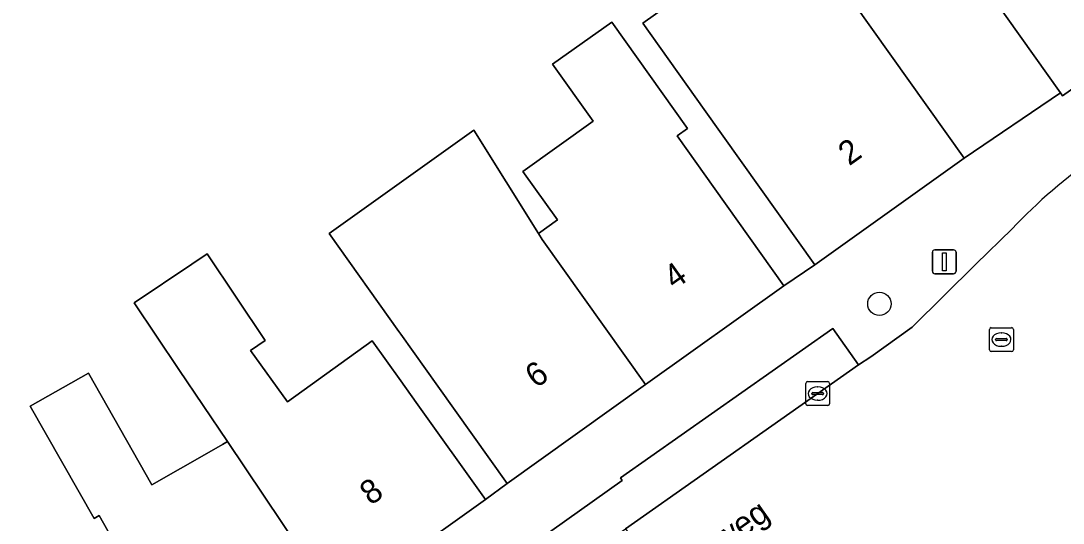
# Model space of a CAD drawing. Extents: x 161838 to 162344, y 381620 to 382160.
# Drawn here: x 161984.06 to 162027.79, y 381958.41 to 381979.46 of the extents above; entities that cross this region are included whole.
import ezdxf

# ---------------------------------------------------------------- set-up
doc = ezdxf.new("R2010")
doc.units = 0
for name, color, linetype in [('IMGEO_Boom', 7, 'Continuous'), ('IMGEO_Erf', 7, 'Continuous'), ('IMGEO_Kolk', 7, 'Continuous'), ('IMGEO_Lichtmast', 7, 'Continuous'), ('IMGEO_Openbare_ruimte_label', 7, 'Continuous'), ('IMGEO_Pand', 7, 'Continuous'), ('IMGEO_Pand_nummerreeks', 7, 'Continuous'), ('IMGEO_Parkeervlak_open', 7, 'Continuous'), ('IMGEO_Rijbaan_lokaal_open', 7, 'Continuous'), ('IMGEO_Rioolput', 7, 'Continuous'), ('IMGEO_Voetpad_open', 7, 'Continuous')]:
    doc.layers.add(name, color=color, linetype=linetype)

msp = doc.modelspace()

# ---------------------------------------------------------------- linework, layer by layer
at = {"layer": 'IMGEO_Boom'}
msp.add_circle((162020.08, 381967.6), 0.489, dxfattribs=at)
at = {"layer": 'IMGEO_Erf'}
msp.add_lwpolyline([(161988.92, 381955.966), (161987.349, 381958.724), (161987.136, 381958.603), (161984.457, 381963.308), (161986.895, 381964.696), (161989.559, 381960.019), (161991.967, 381961.39), (161992.526, 381961.708), (161992.731, 381961.825), (161990.696, 381964.855), (161988.821, 381967.646), (161991.235, 381969.267), (161991.877, 381969.698), (161994.317, 381966.065), (161993.698, 381965.649), (161995.244, 381963.494), (161998.796, 381966.044), (162000.007, 381964.371), (162000.65, 381963.47), (162003.552, 381959.398), (162004.459, 381960.074), (162001.557, 381964.146), (162000, 381966.33), (161999.916, 381966.448), (161996.996, 381970.544), (162003.07, 381974.874), (162005.776, 381970.545), (162006.579, 381971.117), (162005.126, 381973.155), (162008.07, 381975.253), (162006.368, 381977.641), (162008.849, 381979.41), (162012.028, 381974.95), (162011.593, 381974.64), (162013.172, 381972.425), (162016.075, 381968.353), (162017.37, 381969.238), (162012.728, 381975.752), (162010.152, 381979.367), (162013.737, 381981.922)], dxfattribs=at)
at = {"layer": 'IMGEO_Kolk'}
for p, q in [((162016.989, 381963.414), (162016.989, 381964.266)), ((162017.064, 381964.34), (162017.916, 381964.34)), ((162017.477, 381964.12), (162017.502, 381964.12)), ((162017.99, 381964.266), (162017.99, 381963.414)), ((162017.248, 381963.834), (162017.248, 381963.846)), ((162017.686, 381963.797), (162017.288, 381963.797)), ((162017.291, 381963.883), (162017.689, 381963.883)), ((162017.732, 381963.846), (162017.732, 381963.834)), ((162017.916, 381963.34), (162017.064, 381963.34)), ((162017.5, 381963.56), (162017.475, 381963.56))]:
    msp.add_line(p, q, dxfattribs=at)
for points in [[(162016.989, 381963.414), (162016.989, 381964.266)], [(162017.064, 381964.34), (162017.916, 381964.34)], [(162017.99, 381964.266), (162017.99, 381963.414)], [(162017.916, 381963.34), (162017.064, 381963.34)]]:
    msp.add_lwpolyline(points, dxfattribs=at)
for centre, radius, start, end in [((162017.066, 381964.264), 0.0765, 91.552, 178.448), ((162017.066, 381964.264), 0.0765, 91.552, 178.448), ((162017.914, 381964.264), 0.0765, 1.552, 88.448), ((162017.914, 381964.264), 0.0765, 1.552, 88.448), ((162017.288, 381963.843), 0.0403, 85.8775, 175.7526), ((162017.285, 381963.833), 0.0366, 178.938, 274.7102), ((162017.689, 381963.84), 0.043, 264.8664, 352.4533), ((162017.693, 381963.845), 0.0386, 1.7309, 96.639), ((162017.066, 381963.416), 0.0765, 181.552, 268.448), ((162017.066, 381963.416), 0.0765, 181.552, 268.448), ((162017.914, 381963.416), 0.0765, 271.552, 358.448), ((162017.914, 381963.416), 0.0765, 271.552, 358.448)]:
    msp.add_arc(centre, radius, start, end, dxfattribs=at)
for centre, major_axis, ratio, start_param, end_param in [((162017.476, 381963.84), (-0.387, 0.002), 0.722429, 4.712389, 7.853982), ((162017.501, 381963.84), (-0.39, 0.002), 0.717154, 1.570796, 4.712389)]:
    msp.add_ellipse(centre, major_axis=major_axis, ratio=ratio, start_param=start_param, end_param=end_param, dxfattribs=at)
at = {"layer": 'IMGEO_Lichtmast'}
for p, q in [((162022.305, 381968.964), (162022.305, 381969.764)), ((162022.305, 381969.764), (162022.305, 381968.964)), ((162022.405, 381969.864), (162023.195, 381969.864)), ((162023.195, 381969.864), (162022.405, 381969.864)), ((162023.295, 381969.764), (162023.295, 381968.964)), ((162023.295, 381968.964), (162023.295, 381969.764)), ((162023.195, 381968.864), (162022.405, 381968.864)), ((162022.405, 381968.864), (162023.195, 381968.864))]:
    msp.add_line(p, q, dxfattribs=at)
msp.add_lwpolyline([(162022.725, 381969.739), (162022.875, 381969.739), (162022.875, 381968.989), (162022.725, 381968.989), (162022.725, 381969.739)], dxfattribs=at)
for centre, start, end in [((162022.405, 381969.764), 90, 180), ((162022.405, 381969.764), 90, 180), ((162023.195, 381969.764), 0, 90), ((162023.195, 381969.764), 360, 90), ((162022.405, 381968.964), 180, 270), ((162022.405, 381968.964), 180, 270), ((162023.195, 381968.964), 270, 0), ((162023.195, 381968.964), 270, 0)]:
    msp.add_arc(centre, 0.1, start, end, dxfattribs=at)
at = {"layer": 'IMGEO_Pand'}
for points in [[(162040.582, 381994.632), (162028.222, 381985.965), (162028.031, 381986.231), (162023.191, 381982.763), (162027.675, 381976.439), (162027.763, 381976.315), (162044.198, 381987.972), (162044.947, 381988.503), (162043.64, 381990.335), (162043.453, 381990.598)], [(162023.633, 381973.703), (162018.99, 381980.218), (162017.025, 381982.975), (162014.347, 381981.067), (162013.737, 381981.922), (162010.152, 381979.367), (162012.728, 381975.752), (162017.37, 381969.238)], [(162011.593, 381974.64), (162012.028, 381974.95), (162008.849, 381979.41), (162006.368, 381977.641), (162008.07, 381975.253), (162005.126, 381973.155), (162006.579, 381971.117), (162005.776, 381970.545), (162005.93, 381970.299), (162010.268, 381964.214), (162016.075, 381968.353), (162013.172, 381972.425)], [(162005.776, 381970.545), (162003.07, 381974.874), (161996.996, 381970.544), (161999.916, 381966.448), (162000, 381966.33), (162001.557, 381964.146), (162004.459, 381960.074), (162010.268, 381964.214), (162005.93, 381970.299)], [(161992.731, 381961.825), (161997.314, 381955), (161997.98, 381955.381), (161999.988, 381956.857), (162003.552, 381959.398), (162000.65, 381963.47), (162000.007, 381964.371), (161998.796, 381966.044), (161995.244, 381963.494), (161993.698, 381965.649), (161994.317, 381966.065), (161991.877, 381969.698), (161991.235, 381969.267), (161988.821, 381967.646), (161990.696, 381964.855)], [(161992.731, 381961.825), (161992.526, 381961.708), (161991.967, 381961.39), (161989.559, 381960.019), (161986.895, 381964.696), (161984.457, 381963.308), (161987.136, 381958.603), (161987.349, 381958.724), (161988.92, 381955.966), (161991.394, 381951.62), (161997.314, 381955)]]:
    msp.add_lwpolyline(points, close=True, dxfattribs=at)
at = {"layer": 'IMGEO_Parkeervlak_open'}
msp.add_lwpolyline([(161972.482, 381935.56), (161972.584, 381935.619), (161974.917, 381936.979), (162000, 381951.624), (162005.452, 381955.402), (162009.423, 381958.174), (162019.209, 381965.048), (162018.131, 381966.571), (162009.22, 381960.309), (162009.295, 381960.196), (162002.756, 381955.558), (162000, 381953.557), (161999.035, 381952.878), (161982.723, 381943.483), (161973.533, 381938.154), (161972.911, 381937.782)], dxfattribs=at)
at = {"layer": 'IMGEO_Rijbaan_lokaal_open'}
msp.add_lwpolyline([(162019.699, 381987.686), (162016.287, 381992.222), (162016.072, 381992.055), (162011.974, 381997.652), (162008.706, 381995.389), (162008.587, 381995.307), (162010.905, 381991.921), (162011.519, 381991.023), (162017.025, 381982.975), (162018.99, 381980.218), (162023.633, 381973.703), (162027.675, 381976.439), (162023.191, 381982.763)], close=True, dxfattribs=at)
msp.add_lwpolyline([(162025.649, 381970.744), (162024.131, 381969.266), (162021.458, 381966.619), (162019.719, 381965.377), (162019.209, 381965.048), (162009.423, 381958.174), (162012.054, 381954.611), (162018.349, 381956.152), (162021.392, 381956.878)], dxfattribs=at)
msp.add_arc((162042.038, 381955.244), 22.558, 124.7269, 136.5982, dxfattribs=at)
at = {"layer": 'IMGEO_Rioolput'}
for p, q in [((162024.699, 381965.676), (162024.699, 381966.528)), ((162024.774, 381966.602), (162025.626, 381966.602)), ((162025.187, 381966.382), (162025.212, 381966.382)), ((162025.7, 381966.528), (162025.7, 381965.676)), ((162024.958, 381966.096), (162024.958, 381966.108)), ((162025.396, 381966.059), (162024.998, 381966.059)), ((162025.001, 381966.145), (162025.399, 381966.145)), ((162025.442, 381966.108), (162025.442, 381966.096)), ((162025.626, 381965.602), (162024.774, 381965.602)), ((162025.21, 381965.822), (162025.185, 381965.822))]:
    msp.add_line(p, q, dxfattribs=at)
for points in [[(162024.699, 381965.676), (162024.699, 381966.528)], [(162024.774, 381966.602), (162025.626, 381966.602)], [(162025.7, 381966.528), (162025.7, 381965.676)], [(162025.626, 381965.602), (162024.774, 381965.602)]]:
    msp.add_lwpolyline(points, dxfattribs=at)
for centre, radius, start, end in [((162024.776, 381966.526), 0.0765, 91.552, 178.448), ((162024.776, 381966.526), 0.0765, 91.552, 178.448), ((162025.624, 381966.526), 0.0765, 1.552, 88.448), ((162025.624, 381966.526), 0.0765, 1.552, 88.448), ((162024.998, 381966.105), 0.0403, 85.8775, 175.7526), ((162024.995, 381966.095), 0.0366, 178.938, 274.7102), ((162025.399, 381966.102), 0.043, 264.8664, 352.4533), ((162025.403, 381966.107), 0.0386, 1.7309, 96.639), ((162024.776, 381965.678), 0.0765, 181.552, 268.448), ((162024.776, 381965.678), 0.0765, 181.552, 268.448), ((162025.624, 381965.678), 0.0765, 271.552, 358.448), ((162025.624, 381965.678), 0.0765, 271.552, 358.448)]:
    msp.add_arc(centre, radius, start, end, dxfattribs=at)
for centre, major_axis, ratio, start_param, end_param in [((162025.186, 381966.102), (-0.387, 0.002), 0.722429, 4.712389, 7.853982), ((162025.211, 381966.102), (-0.39, 0.002), 0.717154, 1.570796, 4.712389)]:
    msp.add_ellipse(centre, major_axis=major_axis, ratio=ratio, start_param=start_param, end_param=end_param, dxfattribs=at)
at = {"layer": 'IMGEO_Voetpad_open'}
for points in [[(162044.198, 381987.972), (162027.763, 381976.315), (162027.675, 381976.439), (162023.633, 381973.703), (162017.37, 381969.238), (162016.075, 381968.353), (162010.268, 381964.214), (162004.459, 381960.074), (162003.552, 381959.398), (161999.988, 381956.857), (161997.98, 381955.381), (161997.314, 381955), (161991.394, 381951.62), (161990.45, 381950.969), (161985.242, 381948.014), (161980.473, 381945.309), (161975.721, 381942.613), (161974.954, 381942.172), (161969.673, 381939.049), (161967.538, 381937.787), (161959.912, 381939.177), (161958.703, 381939.397), (161937.628, 381943.237), (161912.446, 381947.826)], [(161972.911, 381937.782), (161973.533, 381938.154), (161982.723, 381943.483), (161999.035, 381952.878), (162000, 381953.557), (162002.756, 381955.558), (162009.295, 381960.196), (162009.22, 381960.309), (162018.131, 381966.571), (162019.209, 381965.048), (162019.719, 381965.377), (162021.458, 381966.619), (162024.131, 381969.266), (162025.649, 381970.744)]]:
    msp.add_lwpolyline(points, dxfattribs=at)
msp.add_arc((162042.038, 381955.244), 22.558, 124.7269, 136.5982, dxfattribs=at)

# ---------------------------------------------------------------- texts
at = {"layer": 'IMGEO_Openbare_ruimte_label'}
msp.add_text('Biesterweg', height=1, rotation=35.1845, dxfattribs=at).set_placement((162010.144, 381954.826))
at = {"layer": 'IMGEO_Pand_nummerreeks'}
for s, rotation, p in [('2', 35.4857, (162018.813, 381973.362)), ('4', 35.4775, (162011.486, 381968.175)), ('6', 35.4784, (162005.678, 381964.037)), ('8', 35.6666, (161998.743, 381959.127))]:
    msp.add_text(s, height=1, rotation=rotation, dxfattribs=at).set_placement(p)

doc.saveas('drawing.dxf')
